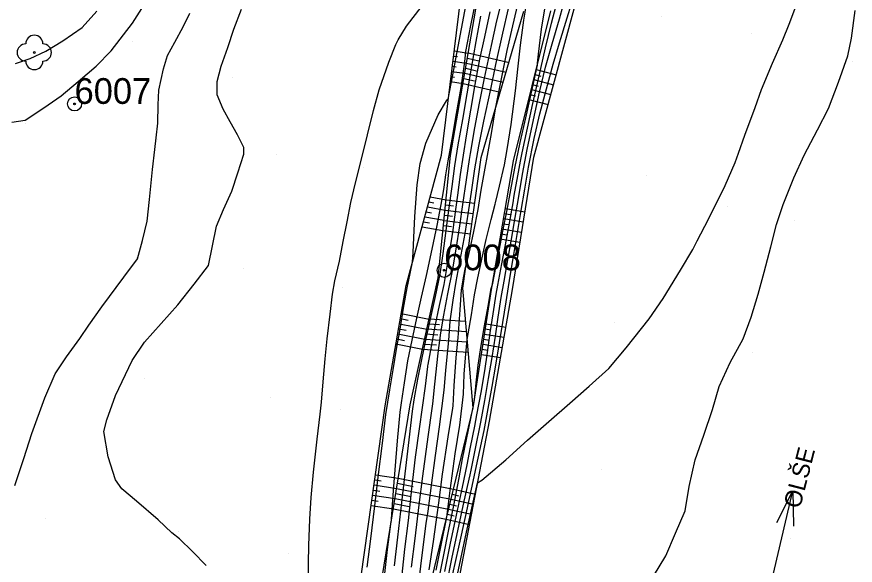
# Model space of a CAD drawing. Extents: x -448957 to -448612, y -1107690 to -1107245.
# Drawn here: x -448714.86 to -448666.02, y -1107404.41 to -1107372.46 of the extents above; entities that cross this region are included whole.
import ezdxf

# ---------------------------------------------------------------- set-up
doc = ezdxf.new("R2010")
doc.units = 0
for name, color, linetype in [('22', 7, 'Continuous'), ('63', 7, 'Continuous'), ('Default', 7, 'Continuous'), ('Vrstva 1', 7, 'Continuous'), ('Vrstva 10', 7, 'Continuous'), ('Vrstva 14', 7, 'Continuous'), ('Vrstva 15', 7, 'Continuous'), ('Vrstva 16', 7, 'Continuous'), ('Vrstva 17', 7, 'Continuous'), ('Vrstva 22', 7, 'Continuous'), ('Vrstva 45', 7, 'Continuous'), ('Vrstva 63', 7, 'Continuous')]:
    doc.layers.add(name, color=color, linetype=linetype)

# ---------------------------------------------------------------- blocks, each defined once
blk = doc.blocks.new('POINT_DISPLAY')
at = {"layer": 'Default'}
blk.add_line((0, 0), (0, 0), dxfattribs=at)
blk = doc.blocks.new('STROM$5')
at = {"layer": '22'}
blk.add_circle((0, 0), 0.5, dxfattribs=at)
for centre, start, end in [((0, 5), 0, 180), ((-5, 0), 90, 270), ((5, 0), 270, 90), ((0, -5), 180, 0)]:
    blk.add_arc(centre, 5, start, end, dxfattribs=at)
blk = doc.blocks.new('PPBP$7')
at = {"layer": '63'}
for radius in [4.12, 0.5]:
    blk.add_circle((0, 0), radius, dxfattribs=at)
blk = doc.blocks.new('TOK')
at = {"layer": 'Default'}
for p, q in [((-5, 50), (0, 70)), ((0, 0), (0, 70)), ((0, 70), (5, 50))]:
    blk.add_line(p, q, dxfattribs=at)

msp = doc.modelspace()

# ---------------------------------------------------------------- linework, layer by layer
at = {"layer": 'Vrstva 10'}
for p, q in [((-448689.59, -1107380.531), (-448688.046, -1107371.576)), ((-448690.317, -1107387.667), (-448689.59, -1107380.531)), ((-448691.944, -1107395.072), (-448690.317, -1107387.667)), ((-448693.58, -1107405.13), (-448691.944, -1107395.072))]:
    msp.add_line(p, q, dxfattribs=at)
at = {"layer": 'Vrstva 14'}
for p, q in [((-448690.131, -1107380.515), (-448688.996, -1107371.287)), ((-448687.809, -1107380.657), (-448685.318, -1107372.133)), ((-448685.927, -1107380.851), (-448683.746, -1107372.113)), ((-448684.748, -1107380.633), (-448682.391, -1107371.986)), ((-448692.179, -1107388.105), (-448690.131, -1107380.515)), ((-448688.89, -1107388.275), (-448687.809, -1107380.657)), ((-448687.203, -1107388.341), (-448685.927, -1107380.851)), ((-448685.997, -1107388.339), (-448684.748, -1107380.633)), ((-448693.406, -1107395.117), (-448692.179, -1107388.105)), ((-448688.287, -1107395.234), (-448688.89, -1107388.275)), ((-448688.287, -1107395.234), (-448687.203, -1107388.341)), ((-448687.336, -1107396.016), (-448685.997, -1107388.339)), ((-448694.793, -1107405.054), (-448693.406, -1107395.117)), ((-448690.665, -1107405.133), (-448688.287, -1107395.234)), ((-448689.113, -1107405.317), (-448687.336, -1107396.016))]:
    msp.add_line(p, q, dxfattribs=at)
at = {"layer": 'Vrstva 15'}
for p, q in [((-448689.421, -1107374.746), (-448689.195, -1107374.779)), ((-448689.385, -1107374.448), (-448688.562, -1107374.569)), ((-448688.562, -1107374.567), (-448686.19, -1107375.116)), ((-448689.458, -1107375.043), (-448688.664, -1107375.161)), ((-448688.664, -1107375.159), (-448686.358, -1107375.693)), ((-448688.613, -1107374.863), (-448687.954, -1107375.016)), ((-448689.531, -1107375.639), (-448688.766, -1107375.752)), ((-448689.495, -1107375.341), (-448689.276, -1107375.374)), ((-448688.715, -1107375.455), (-448688.075, -1107375.603)), ((-448684.6, -1107375.533), (-448683.44, -1107375.836)), ((-448689.568, -1107375.937), (-448689.357, -1107375.968)), ((-448688.817, -1107376.047), (-448688.196, -1107376.191)), ((-448688.766, -1107375.751), (-448686.527, -1107376.27)), ((-448684.745, -1107376.116), (-448683.598, -1107376.415)), ((-448684.672, -1107375.824), (-448684.345, -1107375.91)), ((-448689.605, -1107376.235), (-448688.868, -1107376.344)), ((-448688.868, -1107376.344), (-448686.695, -1107376.847)), ((-448684.89, -1107376.698), (-448683.756, -1107376.994)), ((-448684.818, -1107376.407), (-448684.494, -1107376.491)), ((-448684.963, -1107376.989), (-448684.642, -1107377.072)), ((-448685.036, -1107377.28), (-448683.914, -1107377.573)), ((-448690.787, -1107382.946), (-448689.854, -1107383.119)), ((-448690.944, -1107383.528), (-448689.915, -1107383.718)), ((-448690.865, -1107383.237), (-448690.571, -1107383.291)), ((-448689.885, -1107383.423), (-448689.415, -1107383.48)), ((-448689.854, -1107383.124), (-448688.188, -1107383.327)), ((-448691.022, -1107383.818), (-448690.701, -1107383.878)), ((-448689.945, -1107384.02), (-448689.483, -1107384.076)), ((-448689.915, -1107383.721), (-448688.272, -1107383.921)), ((-448686.45, -1107383.92), (-448686.124, -1107383.974)), ((-448686.399, -1107383.624), (-448685.263, -1107383.813)), ((-448691.179, -1107384.399), (-448690.83, -1107384.464)), ((-448691.101, -1107384.109), (-448689.976, -1107384.316)), ((-448689.976, -1107384.318), (-448688.357, -1107384.516)), ((-448686.551, -1107384.512), (-448686.223, -1107384.566)), ((-448686.5, -1107384.216), (-448685.359, -1107384.406)), ((-448691.258, -1107384.69), (-448690.037, -1107384.915)), ((-448690.037, -1107384.915), (-448688.441, -1107385.11)), ((-448690.006, -1107384.617), (-448689.55, -1107384.672)), ((-448686.601, -1107384.807), (-448685.455, -1107384.998)), ((-448686.702, -1107385.399), (-448685.551, -1107385.59)), ((-448686.651, -1107385.103), (-448686.323, -1107385.158)), ((-448692.467, -1107389.749), (-448690.845, -1107390.069)), ((-448692.57, -1107390.34), (-448690.974, -1107390.655)), ((-448692.518, -1107390.044), (-448692.062, -1107390.134)), ((-448690.905, -1107390.345), (-448690.249, -1107390.388)), ((-448690.84, -1107390.049), (-448688.724, -1107390.186)), ((-448687.519, -1107390.35), (-448686.381, -1107390.538)), ((-448692.622, -1107390.636), (-448692.173, -1107390.724)), ((-448690.971, -1107390.642), (-448688.672, -1107390.791)), ((-448687.566, -1107390.646), (-448687.243, -1107390.7)), ((-448692.725, -1107391.227), (-448692.284, -1107391.314)), ((-448692.674, -1107390.931), (-448691.102, -1107391.241)), ((-448691.101, -1107391.234), (-448688.62, -1107391.396)), ((-448691.036, -1107390.938), (-448690.327, -1107390.984)), ((-448687.659, -1107391.239), (-448687.339, -1107391.292)), ((-448687.612, -1107390.942), (-448686.484, -1107391.13)), ((-448692.777, -1107391.522), (-448691.231, -1107391.827)), ((-448691.231, -1107391.827), (-448688.567, -1107392)), ((-448691.166, -1107391.531), (-448690.405, -1107391.58)), ((-448687.752, -1107391.832), (-448687.435, -1107391.884)), ((-448687.705, -1107391.535), (-448686.587, -1107391.721)), ((-448687.799, -1107392.128), (-448686.69, -1107392.312)), ((-448693.968, -1107399.141), (-448692.639, -1107399.342)), ((-448694.009, -1107399.438), (-448693.633, -1107399.495)), ((-448692.687, -1107399.637), (-448691.782, -1107399.819)), ((-448692.638, -1107399.341), (-448689.429, -1107399.987)), ((-448694.092, -1107400.033), (-448693.72, -1107400.089)), ((-448694.051, -1107399.736), (-448692.735, -1107399.934)), ((-448692.735, -1107399.934), (-448689.569, -1107400.57)), ((-448689.429, -1107399.987), (-448688.148, -1107400.263)), ((-448694.175, -1107400.627), (-448693.807, -1107400.683)), ((-448694.134, -1107400.33), (-448692.831, -1107400.527)), ((-448692.831, -1107400.526), (-448689.709, -1107401.154)), ((-448692.783, -1107400.23), (-448691.891, -1107400.409)), ((-448689.569, -1107400.571), (-448688.26, -1107400.853)), ((-448689.499, -1107400.279), (-448689.125, -1107400.36)), ((-448694.217, -1107400.924), (-448692.928, -1107401.119)), ((-448692.928, -1107401.119), (-448689.849, -1107401.738)), ((-448692.879, -1107400.823), (-448692, -1107400.999)), ((-448689.639, -1107400.863), (-448689.257, -1107400.945)), ((-448689.779, -1107401.446), (-448689.39, -1107401.53)), ((-448689.709, -1107401.154), (-448688.373, -1107401.443)), ((-448689.849, -1107401.738), (-448688.485, -1107402.032))]:
    msp.add_line(p, q, dxfattribs=at)
at = {"layer": 'Vrstva 16'}
for points in [[(-448690.431, -1107404.694), (-448690.1, -1107403.04), (-448689.853, -1107401.799), (-448689.831, -1107401.683), (-448689.819, -1107401.61), (-448689.623, -1107400.064), (-448689.332, -1107397.914), (-448689.048, -1107396.259), (-448688.843, -1107394.437), (-448688.801, -1107393.284), (-448688.703, -1107392.086), (-448688.63, -1107391.271), (-448688.567, -1107390.937), (-448688.384, -1107389.814), (-448688.203, -1107388.666), (-448688.004, -1107387.668), (-448687.734, -1107386.402), (-448687.53, -1107385.437), (-448687.231, -1107384.263), (-448686.99, -1107383.374), (-448686.97, -1107383.304), (-448686.737, -1107382.323), (-448686.447, -1107381.083), (-448686.291, -1107380.183), (-448686.072, -1107378.742), (-448685.82, -1107376.773), (-448685.662, -1107375.326), (-448685.512, -1107374.107), (-448685.325, -1107372.659), (-448685.141, -1107371.482)], [(-448689.373, -1107405.775), (-448689.006, -1107404.034), (-448688.662, -1107402.49), (-448688.312, -1107400.912), (-448688.024, -1107399.616), (-448687.771, -1107399.455), (-448686.37, -1107398.268), (-448685.113, -1107397.132), (-448683.87, -1107396.035), (-448682.653, -1107394.975), (-448681.522, -1107393.979), (-448680.371, -1107392.959), (-448679.363, -1107391.741), (-448678.022, -1107390.054), (-448677.209, -1107388.871), (-448676.201, -1107387.219), (-448675.491, -1107386.014), (-448675.233, -1107385.508), (-448674.563, -1107384.242), (-448673.604, -1107382.291), (-448673.017, -1107380.944), (-448672.822, -1107380.411), (-448672.447, -1107379.355), (-448671.853, -1107377.741), (-448671.477, -1107376.69), (-448670.834, -1107375.157), (-448670.235, -1107373.809), (-448669.867, -1107372.88), (-448669.374, -1107371.554)], [(-448714.977, -1107399.759), (-448714.452, -1107398.185), (-448713.982, -1107396.745), (-448713.226, -1107394.665), (-448712.621, -1107393.258), (-448711.971, -1107392.262), (-448711.197, -1107391.2), (-448710.669, -1107390.425), (-448709.901, -1107389.363), (-448708.628, -1107387.623), (-448707.84, -1107386.562), (-448707.541, -1107385.5), (-448707.266, -1107384.357), (-448707.135, -1107383.098), (-448707.019, -1107381.94), (-448706.947, -1107381.357), (-448706.819, -1107380.2), (-448706.734, -1107379.509), (-448706.655, -1107378.658), (-448706.626, -1107377.588), (-448706.588, -1107376.734), (-448706.316, -1107375.497), (-448706.081, -1107374.714), (-448705.656, -1107373.94), (-448705.162, -1107373.046), (-448704.783, -1107372.24)], [(-448692.87, -1107404.449), (-448692.662, -1107402.772), (-448692.432, -1107400.764), (-448692.246, -1107399.087), (-448692.013, -1107397.1), (-448691.804, -1107395.428), (-448691.717, -1107394.783), (-448691.494, -1107393.565), (-448691.269, -1107392.433), (-448691.009, -1107391.194), (-448690.749, -1107389.985), (-448690.473, -1107388.753), (-448690.195, -1107387.458), (-448690.031, -1107386.257), (-448689.853, -1107384.911), (-448689.688, -1107383.725), (-448689.496, -1107382.337), (-448689.339, -1107381.15), (-448689.145, -1107379.928), (-448688.882, -1107378.435), (-448688.625, -1107376.94), (-448688.368, -1107375.448), (-448688.112, -1107373.891), (-448687.834, -1107372.426)]]:
    msp.add_lwpolyline(points, dxfattribs=at)
at = {"layer": 'Vrstva 17'}
for points in [[(-448693.553, -1107406.115), (-448693.261, -1107403.497), (-448693.049, -1107401.865), (-448693.045, -1107401.821), (-448693.037, -1107401.731), (-448692.92, -1107400.059), (-448692.685, -1107397.166), (-448692.522, -1107395.493), (-448692.461, -1107394.955), (-448692.281, -1107393.787), (-448692.081, -1107392.51), (-448691.832, -1107391.291), (-448691.562, -1107390.024), (-448691.281, -1107388.788), (-448690.993, -1107387.525), (-448690.726, -1107386.277), (-448690.375, -1107384.627), (-448690.136, -1107383.404), (-448690.029, -1107382.76), (-448689.971, -1107382.387), (-448689.862, -1107381.667), (-448689.74, -1107380.852), (-448689.511, -1107379.583), (-448689.242, -1107378.091), (-448688.981, -1107376.584), (-448688.76, -1107375.09), (-448688.707, -1107374.475), (-448688.421, -1107372.971), (-448688.085, -1107371.333)], [(-448691.861, -1107404.531), (-448691.653, -1107402.855), (-448691.417, -1107400.885), (-448691.218, -1107399.217), (-448690.903, -1107396.935), (-448690.664, -1107395.278), (-448690.632, -1107395.013), (-448690.502, -1107393.864), (-448690.31, -1107392.052), (-448690.163, -1107390.869), (-448689.986, -1107389.845), (-448689.75, -1107388.596), (-448689.49, -1107387.252), (-448689.275, -1107385.997), (-448689.063, -1107384.639), (-448688.885, -1107383.401), (-448688.674, -1107381.96), (-448688.496, -1107380.774), (-448688.443, -1107380.429), (-448688.177, -1107378.937), (-448687.918, -1107377.49), (-448687.621, -1107376.042), (-448687.219, -1107374.141), (-448686.899, -1107372.701), (-448686.547, -1107371.318)], [(-448697.876, -1107405.549), (-448697.87, -1107404.291), (-448697.86, -1107403.262), (-448697.801, -1107401.72), (-448697.711, -1107400.474), (-448697.576, -1107398.989), (-448697.368, -1107397.072), (-448697.181, -1107395.613), (-448697.104, -1107394.902), (-448697.01, -1107393.731), (-448696.89, -1107392.386), (-448696.774, -1107391.219), (-448696.601, -1107389.791), (-448696.473, -1107388.62), (-448696.338, -1107387.835), (-448696.071, -1107386.693), (-448695.856, -1107385.558), (-448695.626, -1107384.399), (-448695.399, -1107383.288), (-448695.137, -1107382.133), (-448694.791, -1107380.752), (-448694.424, -1107379.334), (-448694.081, -1107377.923), (-448693.745, -1107376.718), (-448693.183, -1107375.101), (-448692.779, -1107374.068), (-448692.653, -1107373.799), (-448692.17, -1107373.013), (-448691.258, -1107371.823)], [(-448694.448, -1107404.526), (-448694.233, -1107402.868), (-448693.997, -1107400.944), (-448693.804, -1107399.286), (-448693.567, -1107397.298), (-448693.364, -1107395.635), (-448693.142, -1107394.189), (-448692.943, -1107393.02), (-448692.739, -1107391.83), (-448692.535, -1107390.661), (-448692.332, -1107389.435), (-448692.131, -1107388.258), (-448691.953, -1107387.418), (-448691.814, -1107386.751), (-448691.783, -1107386.183), (-448691.727, -1107385.313), (-448691.673, -1107384.093), (-448691.542, -1107382.253), (-448691.375, -1107381.015), (-448691.031, -1107379.812), (-448690.313, -1107378.169), (-448689.837, -1107377.364), (-448689.766, -1107377.282), (-448689.73, -1107377.251), (-448689.461, -1107375.835), (-448688.704, -1107371.811)], [(-448690.837, -1107404.683), (-448690.596, -1107403.022), (-448690.276, -1107400.767), (-448690.063, -1107399.109), (-448689.734, -1107396.923), (-448689.469, -1107395.268), (-448689.452, -1107395.12), (-448689.381, -1107393.967), (-448689.26, -1107392.316), (-448689.156, -1107391.165), (-448689.045, -1107389.534), (-448688.967, -1107388.371), (-448688.833, -1107387.659), (-448688.719, -1107387.067), (-448688.606, -1107386.635), (-448688.446, -1107385.972), (-448688.245, -1107384.96), (-448687.993, -1107383.693), (-448687.803, -1107382.551), (-448687.213, -1107379.261), (-448686.982, -1107377.827), (-448686.979, -1107377.814), (-448686.692, -1107376.367), (-448686.29, -1107374.418), (-448685.966, -1107372.979), (-448685.619, -1107371.487)], [(-448690.312, -1107405.463), (-448690.014, -1107403.91), (-448689.694, -1107402.335), (-448689.425, -1107401.033), (-448689.094, -1107399.329), (-448688.892, -1107398.211), (-448688.545, -1107396.521), (-448688.271, -1107395.204), (-448688.228, -1107394.894), (-448688.191, -1107394.622), (-448688.107, -1107393.777), (-448687.99, -1107392.76), (-448687.803, -1107391.612), (-448687.622, -1107390.467), (-448687.412, -1107389.319), (-448687.221, -1107388.293), (-448687.176, -1107388.114), (-448687.142, -1107387.983), (-448686.961, -1107387.067), (-448686.752, -1107385.998), (-448686.541, -1107384.956), (-448686.295, -1107383.708), (-448686.083, -1107382.539), (-448685.854, -1107381.276), (-448685.534, -1107379.787), (-448685.206, -1107378.337), (-448684.827, -1107376.602), (-448684.537, -1107375.282), (-448684.525, -1107375.154), (-448684.465, -1107374.628), (-448684.29, -1107373.174), (-448684.038, -1107371.639)], [(-448689.931, -1107404.776), (-448689.609, -1107403.229), (-448689.246, -1107401.495), (-448688.902, -1107399.864), (-448688.636, -1107398.571), (-448688.427, -1107397.529), (-448688.186, -1107396.303), (-448688.056, -1107395.648), (-448687.82, -1107394.347), (-448687.603, -1107393.086), (-448687.451, -1107392.023), (-448687.282, -1107390.875), (-448687.113, -1107389.76), (-448686.935, -1107388.611), (-448686.843, -1107388.103), (-448686.606, -1107386.855), (-448686.395, -1107385.74), (-448686.17, -1107384.491), (-448685.958, -1107383.302), (-448685.881, -1107382.88), (-448685.675, -1107381.734), (-448685.519, -1107380.869), (-448685.421, -1107380.386), (-448685.111, -1107378.94), (-448684.803, -1107377.514), (-448684.479, -1107376.065), (-448684.075, -1107374.267), (-448683.707, -1107372.821), (-448683.435, -1107371.805)], [(-448689.84, -1107405.613), (-448689.5, -1107403.947), (-448689.168, -1107402.401), (-448688.797, -1107400.685), (-448688.46, -1107399.14), (-448688.438, -1107399.04), (-448688.424, -1107398.972), (-448688.165, -1107397.7), (-448687.837, -1107396.075), (-448687.605, -1107394.806), (-448687.381, -1107393.527), (-448687.177, -1107392.305), (-448686.983, -1107391.067), (-448686.815, -1107389.956), (-448686.639, -1107388.807), (-448686.479, -1107387.869), (-448686.254, -1107386.621), (-448686.042, -1107385.42), (-448685.826, -1107384.147), (-448685.619, -1107382.922), (-448685.397, -1107381.635), (-448685.131, -1107380.189), (-448684.821, -1107378.743), (-448684.406, -1107376.848), (-448684.062, -1107375.402), (-448683.677, -1107374.029), (-448683.257, -1107372.585), (-448683.032, -1107371.803)], [(-448689.455, -1107404.914), (-448689.117, -1107403.369), (-448688.71, -1107401.516), (-448688.37, -1107399.971), (-448687.981, -1107398.166), (-448687.645, -1107396.56), (-448687.398, -1107395.271), (-448687.173, -1107393.993), (-448686.962, -1107392.75), (-448686.752, -1107391.46), (-448686.556, -1107390.261), (-448686.365, -1107389.06), (-448686.118, -1107387.568), (-448685.903, -1107386.306), (-448685.695, -1107385.034), (-448685.484, -1107383.749), (-448685.276, -1107382.508), (-448685.06, -1107381.222), (-448684.729, -1107379.55), (-448684.4, -1107378.105), (-448684.007, -1107376.659), (-448683.615, -1107375.218), (-448683.244, -1107373.968), (-448682.812, -1107372.523), (-448682.556, -1107371.709)], [(-448715.148, -1107378.59), (-448714.371, -1107378.481), (-448713.292, -1107377.763), (-448712.273, -1107377.061), (-448711.287, -1107376.231), (-448710.229, -1107375.335), (-448709.369, -1107374.445), (-448708.112, -1107372.825), (-448707.587, -1107371.969)], [(-448714.936, -1107375.187), (-448714.083, -1107374.888), (-448713.173, -1107374.454), (-448712.174, -1107373.853), (-448711.05, -1107373.089), (-448710.2, -1107372.129)], [(-448703.832, -1107404.431), (-448704.622, -1107403.607), (-448705.393, -1107402.883), (-448705.822, -1107402.529), (-448706.635, -1107401.767), (-448707.883, -1107400.677), (-448708.75, -1107399.955), (-448709.12, -1107399.446), (-448709.543, -1107398.095), (-448709.798, -1107396.615), (-448709.62, -1107395.939), (-448709.121, -1107394.518), (-448708.138, -1107392.493), (-448707.417, -1107391.42), (-448706.458, -1107390.32), (-448705.485, -1107389.246), (-448704.533, -1107388.039), (-448703.698, -1107386.952), (-448703.458, -1107385.81), (-448703.231, -1107384.665), (-448702.816, -1107383.696), (-448702.344, -1107382.609), (-448701.984, -1107381.558), (-448701.629, -1107380.457), (-448701.633, -1107380.075), (-448702.005, -1107379.333), (-448702.436, -1107378.586), (-448702.844, -1107377.839), (-448703.182, -1107377.015), (-448703.191, -1107376.22), (-448702.965, -1107375.328), (-448702.567, -1107374.245), (-448702.211, -1107373.186), (-448701.771, -1107372.007)], [(-448692.524, -1107406.06), (-448692.25, -1107403.485), (-448692.052, -1107401.808), (-448691.842, -1107399.955), (-448691.632, -1107398.12), (-448691.398, -1107396.459), (-448691.061, -1107393.973), (-448690.921, -1107392.824), (-448690.918, -1107392.797), (-448690.905, -1107392.723), (-448690.711, -1107391.66), (-448690.491, -1107390.485), (-448690.236, -1107389.286), (-448689.97, -1107388.049), (-448689.726, -1107386.652), (-448689.521, -1107385.398), (-448689.45, -1107384.869), (-448689.29, -1107383.682), (-448689.176, -1107382.842), (-448689.013, -1107381.655), (-448688.666, -1107379.398), (-448688.41, -1107377.906), (-448688.153, -1107376.412), (-448687.889, -1107374.93), (-448687.605, -1107373.62), (-448687.29, -1107372.179)], [(-448691.521, -1107406.056), (-448691.227, -1107403.661), (-448691.008, -1107401.987), (-448690.909, -1107401.261), (-448690.694, -1107399.603), (-448690.482, -1107398.01), (-448690.232, -1107396.354), (-448689.971, -1107394.217), (-448689.87, -1107393.066), (-448689.81, -1107392.471), (-448689.704, -1107391.32), (-448689.615, -1107390.199), (-448689.449, -1107388.972), (-448689.26, -1107387.879), (-448689.029, -1107386.631), (-448688.752, -1107385.092), (-448688.551, -1107383.832), (-448688.36, -1107382.531), (-448688.176, -1107381.309), (-448687.957, -1107380.003), (-448687.654, -1107378.542), (-448687.25, -1107376.681), (-448686.954, -1107375.237), (-448686.549, -1107373.406), (-448686.222, -1107371.967)], [(-448677.772, -1107405.052), (-448677.064, -1107403.86), (-448676.499, -1107402.539), (-448675.931, -1107401.239), (-448675.697, -1107399.82), (-448675.351, -1107398.278), (-448674.835, -1107396.828), (-448674.342, -1107395.339), (-448673.944, -1107393.991), (-448673.316, -1107392.609), (-448672.551, -1107391.225), (-448672.078, -1107389.964), (-448671.678, -1107388.628), (-448671.325, -1107387.337), (-448670.949, -1107385.853), (-448670.609, -1107384.559), (-448670.231, -1107383.399), (-448669.606, -1107381.837), (-448668.99, -1107380.519), (-448668.217, -1107379.036), (-448667.584, -1107377.796), (-448667, -1107376.259), (-448666.455, -1107374.729), (-448666.249, -1107373.706), (-448666.024, -1107372.092)]]:
    msp.add_lwpolyline(points, dxfattribs=at)

# ---------------------------------------------------------------- block references
at = {"layer": 'Vrstva 1', "xscale": 0.1, "yscale": 0.10000000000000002}
for p in [(-448690.131, -1107380.515), (-448689.59, -1107380.531), (-448687.809, -1107380.657), (-448685.927, -1107380.851), (-448684.748, -1107380.633), (-448690.317, -1107387.667), (-448692.179, -1107388.105), (-448688.89, -1107388.275), (-448687.203, -1107388.341), (-448685.997, -1107388.339), (-448693.406, -1107395.117), (-448691.944, -1107395.072), (-448688.287, -1107395.234), (-448688.287, -1107395.234), (-448687.336, -1107396.016)]:
    msp.add_blockref('POINT_DISPLAY', p, dxfattribs=at)
at = {"layer": 'Vrstva 14', "xscale": 0.1, "yscale": 0.10000000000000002}
for p in [(-448677.303, -1107372.459), (-448672.071, -1107373.407), (-448708.099, -1107373.88), (-448666.189, -1107375.082), (-448702.296, -1107375.974), (-448714.337, -1107378.703), (-448706.664, -1107379.602), (-448699.721, -1107380.467), (-448694.693, -1107381.235), (-448678.201, -1107381.696), (-448673.453, -1107383.54), (-448669.577, -1107384.337), (-448707.89, -1107386.498), (-448701.664, -1107387.098), (-448695.9, -1107388.217), (-448680.039, -1107390.262), (-448672.034, -1107392.013), (-448707.429, -1107393.548), (-448700.066, -1107394.629), (-448695.99, -1107395.322), (-448680.827, -1107398.823), (-448713.192, -1107401.702), (-448705.434, -1107402.422), (-448669.812, -1107402.829), (-448699.025, -1107403.75)]:
    msp.add_blockref('POINT_DISPLAY', p, dxfattribs=at)
at = {"layer": 'Vrstva 22', "xscale": 0.1, "yscale": 0.10000000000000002}
msp.add_blockref('STROM$5', (-448713.84, -1107374.538), dxfattribs=at)
at = {"layer": 'Vrstva 45', "xscale": 0.09999999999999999, "yscale": 0.1, "rotation": -13.276593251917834}
msp.add_blockref('TOK', (-448671.258, -1107406.897), dxfattribs=at)
at = {"layer": 'Vrstva 63', "xscale": 0.1, "yscale": 0.10000000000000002}
for p in [(-448711.495, -1107377.533), (-448689.965, -1107387.227)]:
    msp.add_blockref('PPBP$7', p, dxfattribs=at)

# ---------------------------------------------------------------- texts
at = {"layer": 'Vrstva 45'}
msp.add_text('OLŠE', height=1, rotation=75.591, dxfattribs=at).set_placement((-448669.242, -1107401.155))
at = {"layer": 'Vrstva 63'}
for s, p in [('6007', (-448711.495, -1107377.533)), ('6008', (-448689.965, -1107387.227))]:
    msp.add_text(s, height=1.5, dxfattribs=at).set_placement(p)

doc.saveas('drawing.dxf')
